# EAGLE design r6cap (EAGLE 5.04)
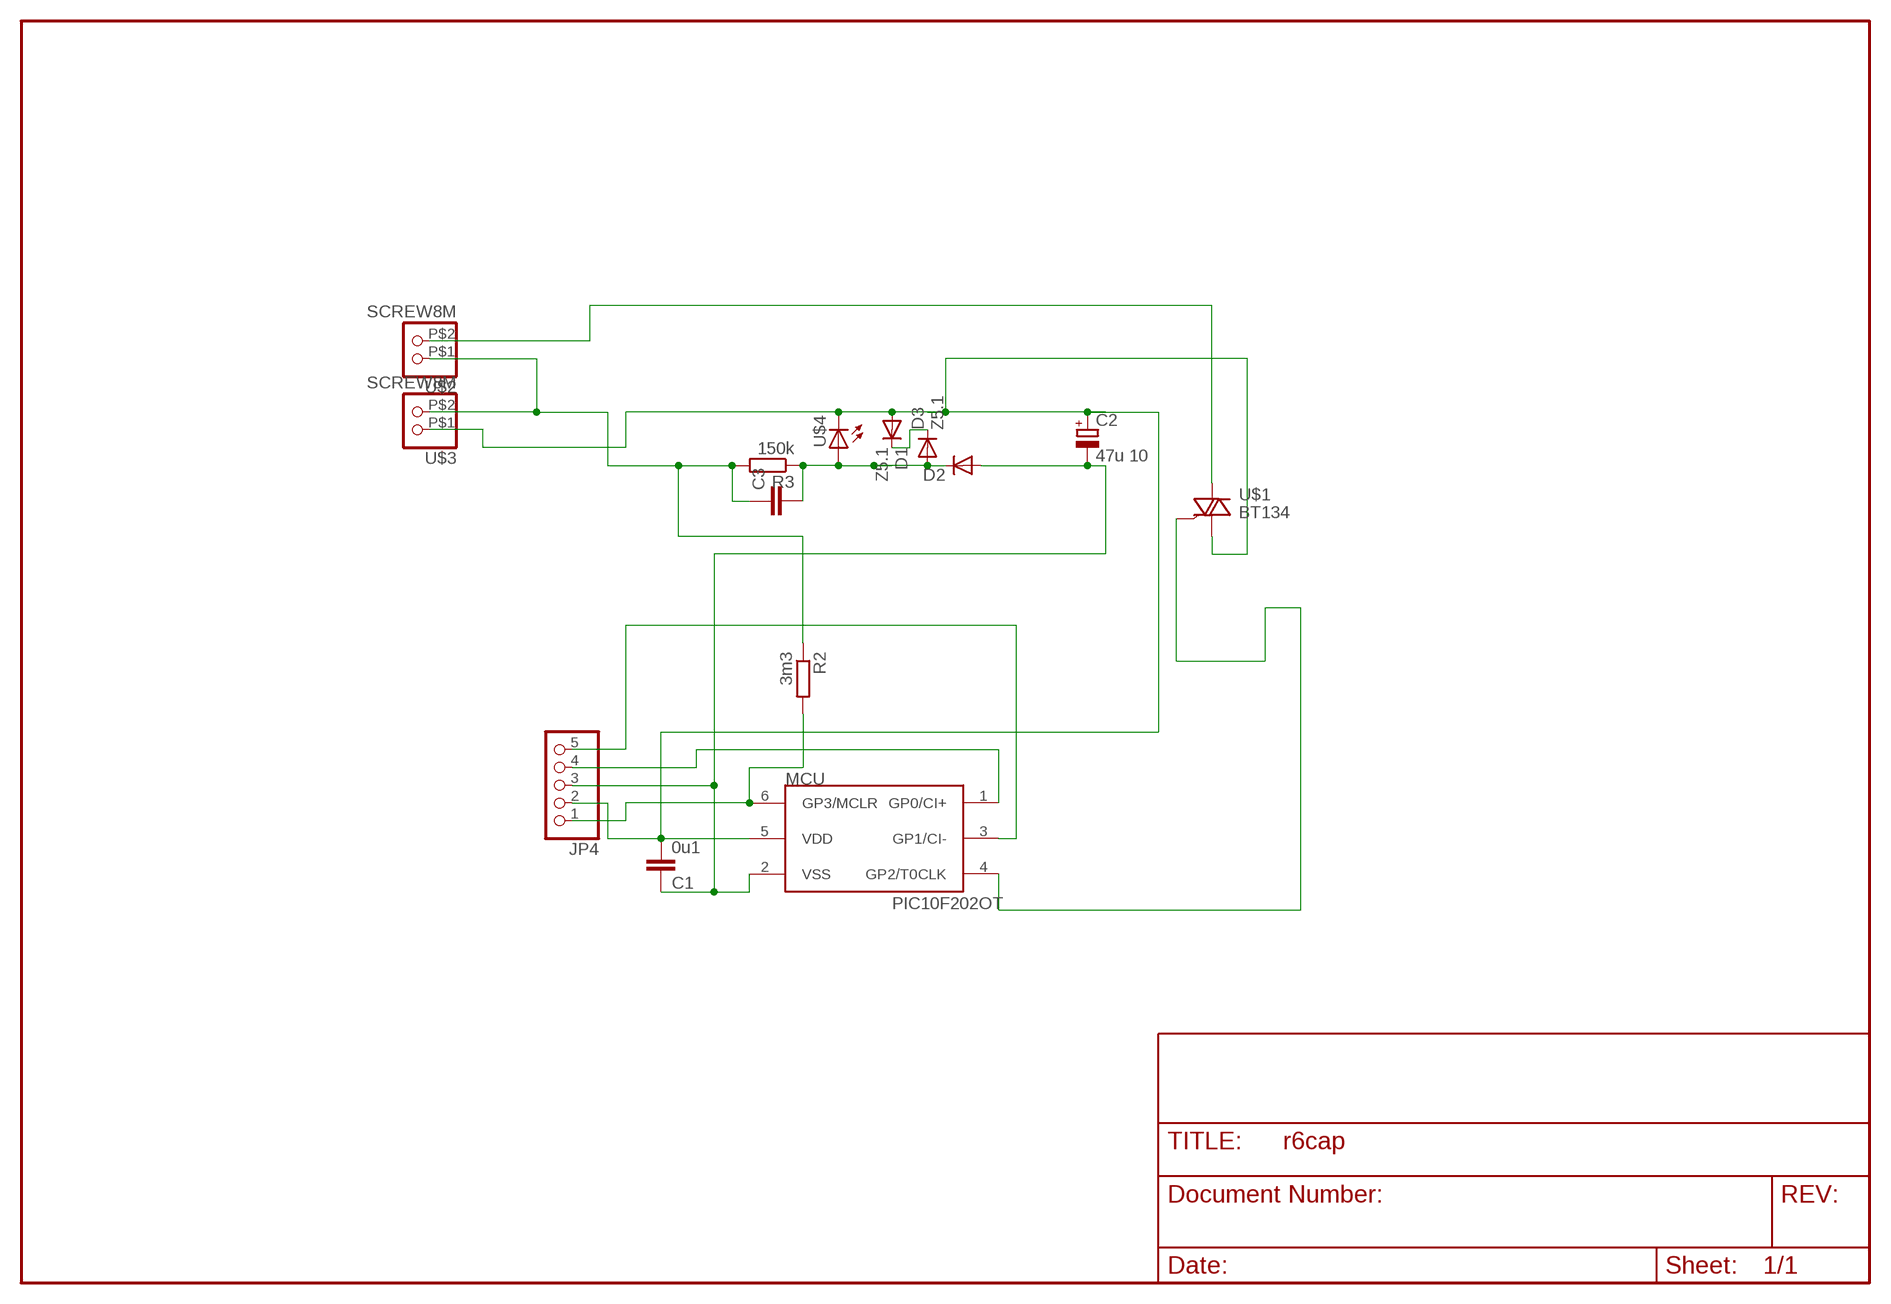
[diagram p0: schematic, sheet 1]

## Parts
C1  0u1  C-EUC0805  [C0805]
C2  47u 10  CPOL-EUE2-5  [E2-5]
C3  C-EU102-064X133  [C102-064X133]
D1  Z5.1  DIODE-D-5  [D-5]
D2  DIODE-MINIMELF  [MINIMELF]
D3  Z5.1  DIODE-MINIMELF  [MINIMELF]
JP4  PINHD-1X5  [1X05]
MCU  PIC10F202OT  [SOT23-6]
R2  3m3  R-EU_R1206  [R1206]
R3  150k  R-EU_R1206  [R1206]
U$1  BT134  [SOT223]
U$2  SCREW8M  [8MM]
U$3  SCREW8M  [8MM]
U$4  LED5MM  [LED5MM]

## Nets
AC(N): C3.1 R2.1 R3.2 U$2.P$1 U$3.P$2
GATE: MCU.4(GP2/T0CLK) U$1.P$3(G)
GP0: JP4.4 MCU.1(GP0/CI+)
GP1: JP4.5 MCU.3(GP1/CI-)
GP3: JP4.1 MCU.6(GP3/MCLR) R2.2
LOAD: U$1.P$2(A2) U$2.P$2
N$2: C3.2 D2.C D3.A R3.1 U$4.A
N$3: D1.C D3.C
VDD/L: C1.2 C2.+ D1.A JP4.2 MCU.5(VDD) U$1.P$1(A1) U$3.P$1 U$4.K(C)
VSS: C1.1 C2.- D2.A JP4.3 MCU.2(VSS)

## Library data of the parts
C1 = rcl:C-EU: CAPACITOR, European symbol
C2 = rcl:CPOL-EU: POLARIZED CAPACITOR, European symbol
C3 = rcl-2:C-EU: CAPACITOR, European symbol
D1-D3 = diode:DIODE-: DIODE
JP4 = pinhead(2):PINHD-1X5: PIN HEADER
MCU = microchip-3:PIC10F2*: uPC nW 0,25/0,5k Program Flash memory Comparator
R2 R3 = rcl:R-EU_: RESISTOR, European symbol
U$1 = triggered_devices:BT134
U$2 U$3 = pinhead(2):SCREW8M
U$4 = led(3):LED: LED

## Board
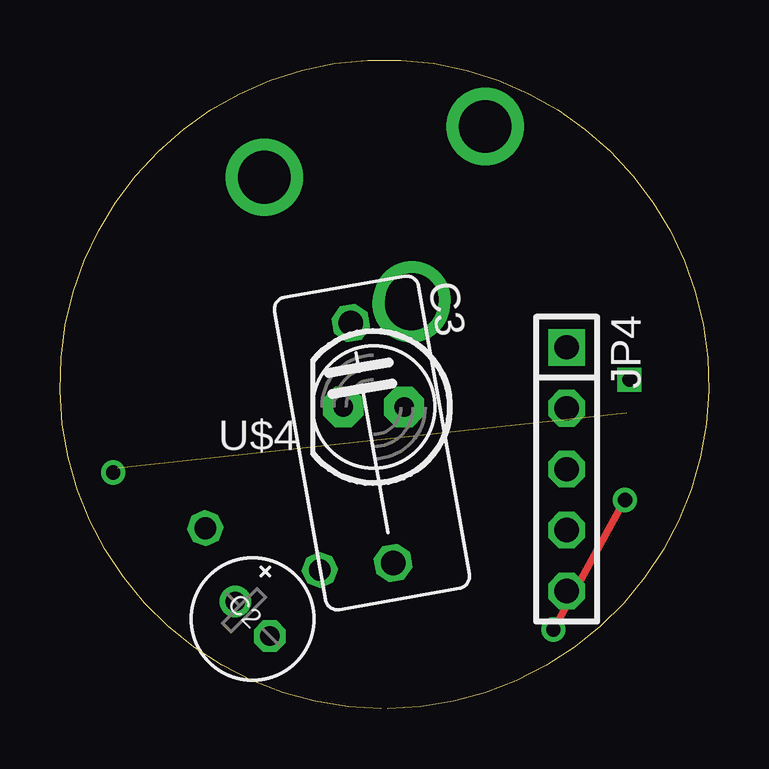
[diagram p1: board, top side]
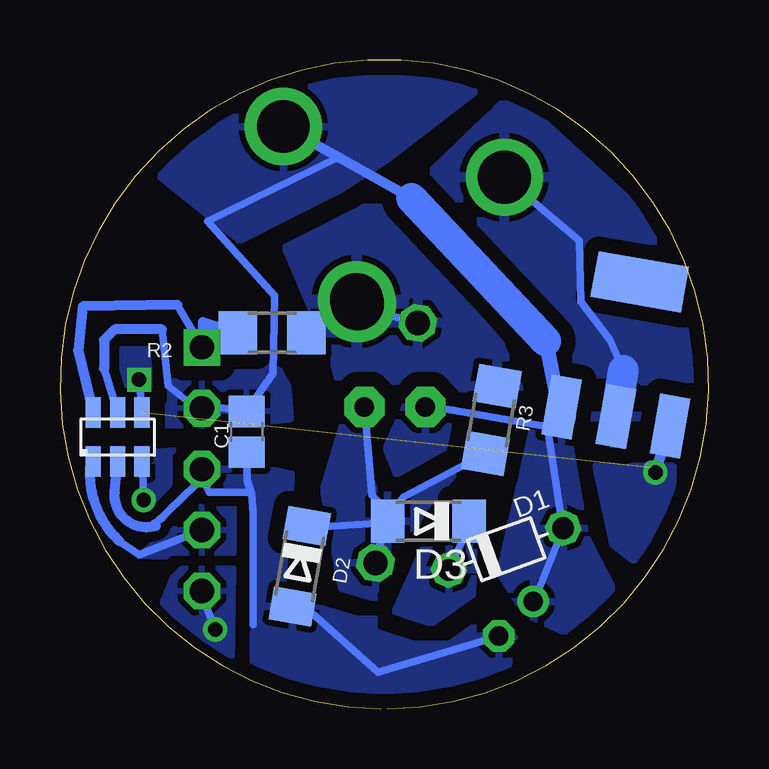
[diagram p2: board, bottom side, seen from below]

Size 27.04 x 27.03 mm. Coordinates in mm from the lower left corner, seen from the top.
Outline: 13.4,0 arc-359 13.65,0
Copper layers (1*16): Top 0.035mm / dielectric 1.5mm / Bottom 0.035mm
Design rules "default": minimum track width 10mil, minimum drill 24mil, track to track 8mil, track to pad 8mil, pad to pad 8mil, via to via 8mil, smd to smd 8mil, copper to edge 8mil, drill to drill 8mil, minimum pad ring 10mil, minimum via ring 8mil, stop-mask expansion 4mil, vias tented up to drill 0mil, thermal gap 10mil

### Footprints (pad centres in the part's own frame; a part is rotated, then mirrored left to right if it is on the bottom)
C0805 = smd 1.3 x 1.5: 1 -0.85,0; 2 0.85,0
E2-5 = drill 0.813 pad 1.27 round: + -1.016,0 | drill 0.813 pad 1.27 octagon: - 1.016,0
C102-064X133 = drill 1.016 octagon: 1 -5.08,0; 2 5.08,0
D-5 = drill 0.9 octagon: A 2.54,0; C -2.54,0
MINIMELF = smd 1.4 x 1.8: A 1.7,0; C -1.7,0
1X05 = drill 1.016 square: 1 -5.08,0 | drill 1.016 octagon: 2 -2.54,0; 3 0,0; 4 2.54,0; 5 5.08,0
SOT23-6 = smd 0.635 x 1.27: 1 -1.016,-1.016; 2 0,-1.016; 3 1.016,-1.016; 4 1.016,1.016; 5 0,1.016; 6 -1.016,1.016
R1206 = smd 1.6 x 1.803: 1 -1.422,0; 2 1.422,0
SOT223 = smd 1.27 x 2.54: P$1 0.7,1.3; P$2 3,1.3; P$3 5.3,1.3 | smd 3.81 x 1.93: P$4 3,7
8MM = drill 2.2 round: P$1 -4,0; P$2 4,0
LED5MM = drill 0.813 pad 1.676 octagon: A -1.27,0; K 1.27,0

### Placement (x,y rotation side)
C1  19.26,11.54 90 bottom
C2  8.03,3.75 315 top
C3  13.01,11.08 280 top
D1  8.45,6.66 20 bottom
D2  17.05,5.94 260 bottom
D3  11.68,7.81 180 bottom
JP4  21.13,9.98 270 top
MCU  24.64,11.32 0 bottom
R2  18.2,15.66 180 bottom
R3  9.06,12.04 80 bottom
U$1  7.05,11.42 350 bottom
U$2  11.6,19.6 140.4 top
U$3  16.19,20.57 247.3 top
U$4  13.08,12.57 180 top

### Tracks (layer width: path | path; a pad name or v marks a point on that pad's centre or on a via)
AC(N)
  Bottom 0.305: C3.1 14.54,16.7 U$3.P$2 14.98,16.7 | 14.98,16.7 U$2.P$1 | R2.1 16.7,15.62 14.98,16.7
  pour Bottom (isolate 0.61, rank 3): 13.59,20.83 18.35,20.95 15.62,14.54 14.47,10.22 7.87,10.54 7.93,13.4 8.7,15.18
GATE  (via drill 0.6)  (1 unrouted)
  Top 0.305: v23.75,13.72 23.56,13.65
  Bottom 0.305: MCU.4 v23.75,13.72
  Bottom 0.406: v2.22,9.84 U$1.P$3
  Bottom 0.61: v2.22,9.84 2.41,10.03
  pour Bottom (isolate 0.61): 1.46,10.1 4.7,10.1 4,6.86 2.85,5.97 1.71,8.38 1.52,9.21
  pour Bottom (isolate 0.406, rank 2): 23.36,13.4 23.3,13.46 23.3,14.99 24.51,14.99 24.51,13.4 24.44,13.46 24.13,13.46
GP0
  Bottom 0.305: JP4.4 23.75,6.41 24.57,6.99
  Bottom 0.406: MCU.1 25.78,10.1 arc-50 24.57,6.99
  pour Bottom (isolate 0.406, rank 2): 19.81,8.45 19.81,6.48 19.94,6.29 22.16,6.29 23.75,6.35 21.65,8.26 21.46,8.45
GP1  (via drill 0.6)
  Top 0.305: v20.57,3.3 v23.56,8.7
  Bottom 0.305: MCU.3 23.56,8.89 v23.56,8.7 | JP4.5 21.21,4.95 v20.57,3.3
  pour Bottom (isolate 0.406): 19.81,5.84 21.97,5.84 22.35,5.46 22.86,4.25 20.89,2.29 19.87,1.84
  pour Bottom (isolate 0.406, rank 2): 22.29,10.79 22.48,10.6 22.48,9.33 23.24,8.57 23.43,8.57 23.56,8.7 23.56,9.72 22.98,10.29 22.98,10.73
GP3
  Bottom 0.305: JP4.1 22.16,16.83
  Bottom 0.406: MCU.6 26.29,14.92 26.1,16.76 22.16,16.83 | JP4.1 21.08,15.11 21.08,16.11 R2.2
LOAD
  Bottom 0.305: 3.55,14.1 4.12,15.37 5.33,16.95 5.39,19.49 U$2.P$2
  Bottom 1.27: U$1.P$2 3.55,14.1
  pour Bottom (isolate 0.61, rank 3): 2.47,20.38 8.19,25.59 12,21.91 3.36,9.84 0.06,11.62 0.38,16.38
N$2
  Bottom 0.305: U$4.A 14.03,8.89 13.29,8.06 | 13.52,7.75 D3.A 13.4,8 C3.2 | 13.52,7.75 13.29,8.06 | 13.29,8.06 12.7,8.83 R3.1 | D2.C 16.32,7.56 13.52,7.75
  pour Bottom (isolate 0.61, rank 2): 10.09,10.35 11.93,8.26 13.52,4.51 15.3,5.02 16.06,9.14 15.11,12.26 13.46,9.46 12.82,9.53
N$3
  Bottom 0.305: D3.C 9.97,7.62 D1.C
  pour Bottom (isolate 0.61): 9.78,6.73 9.84,4.76 11.55,3.56 13.08,4.06 11.93,6.6
VDD/L
  Bottom 0.305: JP4.2 21.33,12.45 | JP4.2 21.02,12.64 C1.2 18.16,13.97 18.09,17.21 20.89,20.32 15.43,22.98 | 25.21,14.18 MCU.5 | 22.79,15.81 22.54,13.46 21.27,12.45 JP4.2 | U$4.K 11.49,12.57 10.66,12.45 6.73,11.75 | U$1.P$1 6.28,12.51 6.73,11.75 | 6.73,11.75 6.09,7.62 D1.A 7.24,4.57 C2.+
  Bottom 0.406: 12.38,21.27 15.43,22.98 U$3.P$1 | 25.21,14.18 25.21,15.37 24.76,15.81 22.79,15.81
  Bottom 0.61: 6.16,12.19 6.79,15.3
  Bottom 1.27: U$1.P$1 6.16,12.19 | 6.79,15.3 12.38,21.27
  pour Bottom (isolate 0.61, rank 2): 9.59,25.84 15.36,26.73 18.35,25.91 23.43,22.61 19.55,19.49 15.43,21.59 13.46,22.86
  pour Bottom (isolate 0.61, rank 3): 17.9,14.16 18.09,14.29 20.25,14.41 22.54,13.59 22.67,13.53 22.67,11.68 22.54,11.81 19.94,11.75 17.4,12.06 17.52,13.46
  pour Bottom: 10.73,12.38 11.05,10.86 13.01,9.78 13.46,10.86 12.57,12.76
  pour Bottom (isolate 0.61): 5.84,11.3 5.14,7.24 4,5.02 5.58,2.98 7.62,3.94 8.7,5.65 7.36,11.49
VSS
  Bottom 0.305: 22.79,7.94 23.11,7.68 21.4,9.34 JP4.3 21.27,9.91 20.82,9.02 19.11,9.02 19.05,8.95 | 18.98,3.49 18.98,8.19 19.05,8.95 | C1.1 19.24,9.53 19.05,8.95 | C2.- 13.78,1.52 16.76,4.19 D2.A
  Bottom 0.406: MCU.2 24.76,9.02 arc-113 23.05,7.62 23.11,7.68
  pour Bottom (isolate 0.61, rank 3): 17.84,4.38 17.4,9.78 22.35,10.86 19.11,8.64 19.24,1.59 13.97,0.38 11.3,0.76 8.38,1.59 8.06,3.24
